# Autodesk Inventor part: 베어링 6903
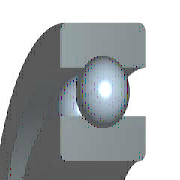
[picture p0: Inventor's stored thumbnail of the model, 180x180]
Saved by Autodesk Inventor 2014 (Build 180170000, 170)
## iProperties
Created: 2012-02
Part Number: 베어링 6903
Material: 강철, 연강
Description: 깊은 그루브 볼 베어링
Document SubType Name: Modeling
Standard: KS B 2023
Designer: mduedu
Standards Organization: KS
Language: ko-KR
Size Designation: 6003 - 17 x 35 x 10
Categories: <MemberInstance><Categories><Category DisplayName="샤프트 부품" InternalName="7f7aeb1f-a693-4053-b835-cee3144e0d98" Mnemonic="SHFT"><Category DisplayName="베어링" Inter
Density: 7.86 g/cm^3
Mass: 16.0417 g
Surface Area: 30.969 cm^2
Volume: 2.04093 cm^3
Appearance: 터키옥색
IsCustomPart: 1
Author: mduedu
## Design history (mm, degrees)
sketch "스케치" dims "d0" = 3.38 (= -0.26 x WD + 0.26 x BD)
  geometry: L1 (1.81, 11.75)-(5.19, 11.75); L2 (3.5, 11.75)-(3.5, 10.06); L3 (3.5, 11.75)-(3.5, 13.44); L4 (2.244, 10.619)-(0, 10.619); L5 (0, 8.5)-(7, 8.5); L6 (2.244, 12.881)-(0, 12.881); L7 (0, 15)-(7, 15); L8 (7, 8.5)-(7, 10.619); L9 (4.756, 10.619)-(7, 10.619); L10 (4.756, 12.881)-(7, 12.881); L11 (7, 15)-(7, 12.881); L12 (-2, 0)-(12, 0) reference; L13 (0, 7.2)-(0, 16.3) reference; 1 other entity
  constraints: 22 end point, 4 point on line, 2 collinear, 2 perpendicular, 2 symmetric about line, 1 midpoint, 1 parallel, 14 other
  dimensions: "d9" = 17 diameter of L5 L12 (= WD); "d11" = 30 diameter of L7 L12 (= BD); "d12" = 7 distance between parallel lines of L8 L13 (= KB); "d13" = 21.238 diameter of L9 L12 (= 0.326 x BD + 0.674 x WD)
revolve "본체" stored, may be unused: angle "d6" = 90 deg
revolve "볼" stored, may be unused: angle "d7" = 90 deg
pattern_circular "IDS_ARRAYBALL[SIMPL:T]" dims angle "d3" = 360 deg
body "Solid1"
fillet "모깎기1" dims "d1" = 0.3 (= KRS)
other parameters: "WD" = 17 [user parameter; used in 5 equation terms], "BD" = 30 [user parameter; used in 5 equation terms], "KB" = 7 [user parameter; used in 1 equation term], "KRS" = 0.3 [user parameter; used in 1 equation term], "d4" = 0, "d5" = 0, "d8" = 0, "d14" = 0, "d15" = 0, "BBA" = 0 [user parameter], "BC0" = 3250000 [user parameter], "BC" = 6050000 [user parameter], "BR" = 15 (= 0.5 x BD) [user parameter], "WR" = 8.5 (= 0.5 x WD) [user parameter]
